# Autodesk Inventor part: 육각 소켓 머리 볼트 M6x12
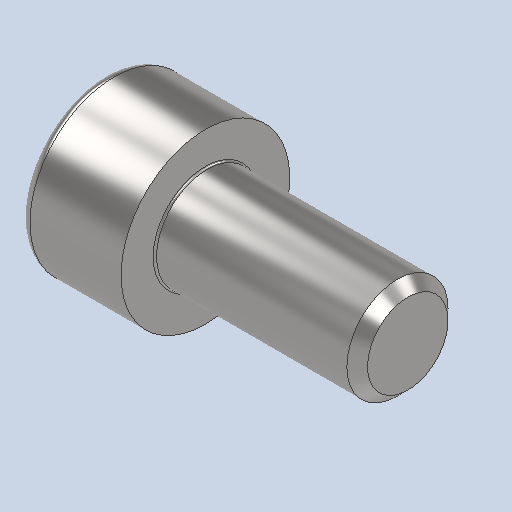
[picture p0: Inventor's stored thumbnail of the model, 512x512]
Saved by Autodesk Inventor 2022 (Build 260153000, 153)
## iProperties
Created: 2024-07
Part Number: 육각 소켓 머리 볼트 M6x12
Material: 강철, 연강
Description: 6각머리 태핑 나사
Document SubType Name: Modeling
Designer: PC-01
Density: 7.85 g/cm^3
Appearance: 기본값
Author: jhkim
Sending System: Autodesk Inventor 2025
Preprocessor: ST-DEVELOPER v20
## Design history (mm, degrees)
feature "Solid1"
node "솔리드1"
